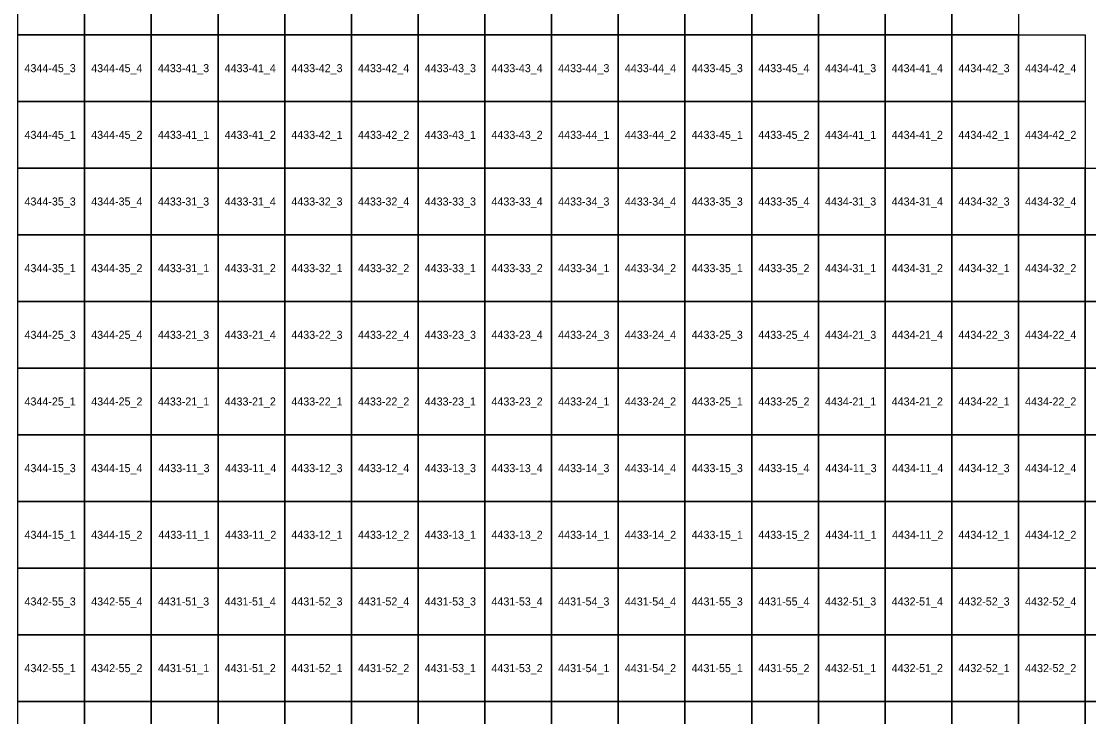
# Model space of a CAD drawing. Extents: x 312500 to 765000, y 172500 to 440000.
# Drawn here: x 595129 to 635129, y 369429 to 395507 of the extents above; entities that cross this region are included whole.
import ezdxf

# ---------------------------------------------------------------- set-up
doc = ezdxf.new("R2010")
doc.units = 0
doc.layers.add('Topo5_ramis_TKS2025', color=7, linetype='Continuous')
doc.layers.add('Topo5_ramis_TKS2025_Nr', color=7, linetype='Continuous')

msp = doc.modelspace()

# ---------------------------------------------------------------- linework, layer by layer
at = {"layer": 'Topo5_ramis_TKS2025'}
for points in [[(595000, 395000), (595000, 397500), (597500, 397500), (597500, 395000), (595000, 395000)], [(597500, 395000), (597500, 397500), (600000, 397500), (600000, 395000), (597500, 395000)], [(600000, 395000), (600000, 397500), (602500, 397500), (602500, 395000), (600000, 395000)], [(602500, 395000), (602500, 397500), (605000, 397500), (605000, 395000), (602500, 395000)], [(605000, 395000), (605000, 397500), (607500, 397500), (607500, 395000), (605000, 395000)], [(607500, 395000), (607500, 397500), (610000, 397500), (610000, 395000), (607500, 395000)], [(610000, 395000), (610000, 397500), (612500, 397500), (612500, 395000), (610000, 395000)], [(612500, 395000), (612500, 397500), (615000, 397500), (615000, 395000), (612500, 395000)], [(615000, 395000), (615000, 397500), (617500, 397500), (617500, 395000), (615000, 395000)], [(617500, 395000), (617500, 397500), (620000, 397500), (620000, 395000), (617500, 395000)], [(620000, 395000), (620000, 397500), (622500, 397500), (622500, 395000), (620000, 395000)], [(622500, 395000), (622500, 397500), (625000, 397500), (625000, 395000), (622500, 395000)], [(625000, 395000), (625000, 397500), (627500, 397500), (627500, 395000), (625000, 395000)], [(627500, 395000), (627500, 397500), (630000, 397500), (630000, 395000), (627500, 395000)], [(630000, 395000), (630000, 397500), (632500, 397500), (632500, 395000), (630000, 395000)], [(595000, 392500), (595000, 395000), (597500, 395000), (597500, 392500), (595000, 392500)], [(597500, 392500), (597500, 395000), (600000, 395000), (600000, 392500), (597500, 392500)], [(600000, 392500), (600000, 395000), (602500, 395000), (602500, 392500), (600000, 392500)], [(602500, 392500), (602500, 395000), (605000, 395000), (605000, 392500), (602500, 392500)], [(605000, 392500), (605000, 395000), (607500, 395000), (607500, 392500), (605000, 392500)], [(607500, 392500), (607500, 395000), (610000, 395000), (610000, 392500), (607500, 392500)], [(610000, 392500), (610000, 395000), (612500, 395000), (612500, 392500), (610000, 392500)], [(612500, 392500), (612500, 395000), (615000, 395000), (615000, 392500), (612500, 392500)], [(615000, 392500), (615000, 395000), (617500, 395000), (617500, 392500), (615000, 392500)], [(617500, 392500), (617500, 395000), (620000, 395000), (620000, 392500), (617500, 392500)], [(620000, 392500), (620000, 395000), (622500, 395000), (622500, 392500), (620000, 392500)], [(622500, 392500), (622500, 395000), (625000, 395000), (625000, 392500), (622500, 392500)], [(625000, 392500), (625000, 395000), (627500, 395000), (627500, 392500), (625000, 392500)], [(627500, 392500), (627500, 395000), (630000, 395000), (630000, 392500), (627500, 392500)], [(630000, 392500), (630000, 395000), (632500, 395000), (632500, 392500), (630000, 392500)], [(632500, 392500), (632500, 395000), (635000, 395000), (635000, 392500), (632500, 392500)], [(595000, 390000), (595000, 392500), (597500, 392500), (597500, 390000), (595000, 390000)], [(597500, 390000), (597500, 392500), (600000, 392500), (600000, 390000), (597500, 390000)], [(600000, 390000), (600000, 392500), (602500, 392500), (602500, 390000), (600000, 390000)], [(602500, 390000), (602500, 392500), (605000, 392500), (605000, 390000), (602500, 390000)], [(605000, 390000), (605000, 392500), (607500, 392500), (607500, 390000), (605000, 390000)], [(607500, 390000), (607500, 392500), (610000, 392500), (610000, 390000), (607500, 390000)], [(610000, 390000), (610000, 392500), (612500, 392500), (612500, 390000), (610000, 390000)], [(612500, 390000), (612500, 392500), (615000, 392500), (615000, 390000), (612500, 390000)], [(615000, 390000), (615000, 392500), (617500, 392500), (617500, 390000), (615000, 390000)], [(617500, 390000), (617500, 392500), (620000, 392500), (620000, 390000), (617500, 390000)], [(620000, 390000), (620000, 392500), (622500, 392500), (622500, 390000), (620000, 390000)], [(622500, 390000), (622500, 392500), (625000, 392500), (625000, 390000), (622500, 390000)], [(625000, 390000), (625000, 392500), (627500, 392500), (627500, 390000), (625000, 390000)], [(627500, 390000), (627500, 392500), (630000, 392500), (630000, 390000), (627500, 390000)], [(630000, 390000), (630000, 392500), (632500, 392500), (632500, 390000), (630000, 390000)], [(632500, 390000), (632500, 392500), (635000, 392500), (635000, 390000), (632500, 390000)], [(595000, 387500), (595000, 390000), (597500, 390000), (597500, 387500), (595000, 387500)], [(597500, 387500), (597500, 390000), (600000, 390000), (600000, 387500), (597500, 387500)], [(600000, 387500), (600000, 390000), (602500, 390000), (602500, 387500), (600000, 387500)], [(602500, 387500), (602500, 390000), (605000, 390000), (605000, 387500), (602500, 387500)], [(605000, 387500), (605000, 390000), (607500, 390000), (607500, 387500), (605000, 387500)], [(607500, 387500), (607500, 390000), (610000, 390000), (610000, 387500), (607500, 387500)], [(610000, 387500), (610000, 390000), (612500, 390000), (612500, 387500), (610000, 387500)], [(612500, 387500), (612500, 390000), (615000, 390000), (615000, 387500), (612500, 387500)], [(615000, 387500), (615000, 390000), (617500, 390000), (617500, 387500), (615000, 387500)], [(617500, 387500), (617500, 390000), (620000, 390000), (620000, 387500), (617500, 387500)], [(620000, 387500), (620000, 390000), (622500, 390000), (622500, 387500), (620000, 387500)], [(622500, 387500), (622500, 390000), (625000, 390000), (625000, 387500), (622500, 387500)], [(625000, 387500), (625000, 390000), (627500, 390000), (627500, 387500), (625000, 387500)], [(627500, 387500), (627500, 390000), (630000, 390000), (630000, 387500), (627500, 387500)], [(630000, 387500), (630000, 390000), (632500, 390000), (632500, 387500), (630000, 387500)], [(632500, 387500), (632500, 390000), (635000, 390000), (635000, 387500), (632500, 387500)], [(635000, 387500), (635000, 390000), (637500, 390000), (637500, 387500), (635000, 387500)], [(595000, 385000), (595000, 387500), (597500, 387500), (597500, 385000), (595000, 385000)], [(597500, 385000), (597500, 387500), (600000, 387500), (600000, 385000), (597500, 385000)], [(600000, 385000), (600000, 387500), (602500, 387500), (602500, 385000), (600000, 385000)], [(602500, 385000), (602500, 387500), (605000, 387500), (605000, 385000), (602500, 385000)], [(605000, 385000), (605000, 387500), (607500, 387500), (607500, 385000), (605000, 385000)], [(607500, 385000), (607500, 387500), (610000, 387500), (610000, 385000), (607500, 385000)], [(610000, 385000), (610000, 387500), (612500, 387500), (612500, 385000), (610000, 385000)], [(612500, 385000), (612500, 387500), (615000, 387500), (615000, 385000), (612500, 385000)], [(615000, 385000), (615000, 387500), (617500, 387500), (617500, 385000), (615000, 385000)], [(617500, 385000), (617500, 387500), (620000, 387500), (620000, 385000), (617500, 385000)], [(620000, 385000), (620000, 387500), (622500, 387500), (622500, 385000), (620000, 385000)], [(622500, 385000), (622500, 387500), (625000, 387500), (625000, 385000), (622500, 385000)], [(625000, 385000), (625000, 387500), (627500, 387500), (627500, 385000), (625000, 385000)], [(627500, 385000), (627500, 387500), (630000, 387500), (630000, 385000), (627500, 385000)], [(630000, 385000), (630000, 387500), (632500, 387500), (632500, 385000), (630000, 385000)], [(632500, 385000), (632500, 387500), (635000, 387500), (635000, 385000), (632500, 385000)], [(635000, 385000), (635000, 387500), (637500, 387500), (637500, 385000), (635000, 385000)], [(595000, 382500), (595000, 385000), (597500, 385000), (597500, 382500), (595000, 382500)], [(597500, 382500), (597500, 385000), (600000, 385000), (600000, 382500), (597500, 382500)], [(600000, 382500), (600000, 385000), (602500, 385000), (602500, 382500), (600000, 382500)], [(602500, 382500), (602500, 385000), (605000, 385000), (605000, 382500), (602500, 382500)], [(605000, 382500), (605000, 385000), (607500, 385000), (607500, 382500), (605000, 382500)], [(607500, 382500), (607500, 385000), (610000, 385000), (610000, 382500), (607500, 382500)], [(610000, 382500), (610000, 385000), (612500, 385000), (612500, 382500), (610000, 382500)], [(612500, 382500), (612500, 385000), (615000, 385000), (615000, 382500), (612500, 382500)], [(615000, 382500), (615000, 385000), (617500, 385000), (617500, 382500), (615000, 382500)], [(617500, 382500), (617500, 385000), (620000, 385000), (620000, 382500), (617500, 382500)], [(620000, 382500), (620000, 385000), (622500, 385000), (622500, 382500), (620000, 382500)], [(622500, 382500), (622500, 385000), (625000, 385000), (625000, 382500), (622500, 382500)], [(625000, 382500), (625000, 385000), (627500, 385000), (627500, 382500), (625000, 382500)], [(627500, 382500), (627500, 385000), (630000, 385000), (630000, 382500), (627500, 382500)], [(630000, 382500), (630000, 385000), (632500, 385000), (632500, 382500), (630000, 382500)], [(632500, 382500), (632500, 385000), (635000, 385000), (635000, 382500), (632500, 382500)], [(635000, 382500), (635000, 385000), (637500, 385000), (637500, 382500), (635000, 382500)], [(595000, 380000), (595000, 382500), (597500, 382500), (597500, 380000), (595000, 380000)], [(597500, 380000), (597500, 382500), (600000, 382500), (600000, 380000), (597500, 380000)], [(600000, 380000), (600000, 382500), (602500, 382500), (602500, 380000), (600000, 380000)], [(602500, 380000), (602500, 382500), (605000, 382500), (605000, 380000), (602500, 380000)], [(605000, 380000), (605000, 382500), (607500, 382500), (607500, 380000), (605000, 380000)], [(607500, 380000), (607500, 382500), (610000, 382500), (610000, 380000), (607500, 380000)], [(610000, 380000), (610000, 382500), (612500, 382500), (612500, 380000), (610000, 380000)], [(612500, 380000), (612500, 382500), (615000, 382500), (615000, 380000), (612500, 380000)], [(615000, 380000), (615000, 382500), (617500, 382500), (617500, 380000), (615000, 380000)], [(617500, 380000), (617500, 382500), (620000, 382500), (620000, 380000), (617500, 380000)], [(620000, 380000), (620000, 382500), (622500, 382500), (622500, 380000), (620000, 380000)], [(622500, 380000), (622500, 382500), (625000, 382500), (625000, 380000), (622500, 380000)], [(625000, 380000), (625000, 382500), (627500, 382500), (627500, 380000), (625000, 380000)], [(627500, 380000), (627500, 382500), (630000, 382500), (630000, 380000), (627500, 380000)], [(630000, 380000), (630000, 382500), (632500, 382500), (632500, 380000), (630000, 380000)], [(632500, 380000), (632500, 382500), (635000, 382500), (635000, 380000), (632500, 380000)], [(635000, 380000), (635000, 382500), (637500, 382500), (637500, 380000), (635000, 380000)], [(595000, 377500), (595000, 380000), (597500, 380000), (597500, 377500), (595000, 377500)], [(597500, 377500), (597500, 380000), (600000, 380000), (600000, 377500), (597500, 377500)], [(600000, 377500), (600000, 380000), (602500, 380000), (602500, 377500), (600000, 377500)], [(602500, 377500), (602500, 380000), (605000, 380000), (605000, 377500), (602500, 377500)], [(605000, 377500), (605000, 380000), (607500, 380000), (607500, 377500), (605000, 377500)], [(607500, 377500), (607500, 380000), (610000, 380000), (610000, 377500), (607500, 377500)], [(610000, 377500), (610000, 380000), (612500, 380000), (612500, 377500), (610000, 377500)], [(612500, 377500), (612500, 380000), (615000, 380000), (615000, 377500), (612500, 377500)], [(615000, 377500), (615000, 380000), (617500, 380000), (617500, 377500), (615000, 377500)], [(617500, 377500), (617500, 380000), (620000, 380000), (620000, 377500), (617500, 377500)], [(620000, 377500), (620000, 380000), (622500, 380000), (622500, 377500), (620000, 377500)], [(622500, 377500), (622500, 380000), (625000, 380000), (625000, 377500), (622500, 377500)], [(625000, 377500), (625000, 380000), (627500, 380000), (627500, 377500), (625000, 377500)], [(627500, 377500), (627500, 380000), (630000, 380000), (630000, 377500), (627500, 377500)], [(630000, 377500), (630000, 380000), (632500, 380000), (632500, 377500), (630000, 377500)], [(632500, 377500), (632500, 380000), (635000, 380000), (635000, 377500), (632500, 377500)], [(635000, 377500), (635000, 380000), (637500, 380000), (637500, 377500), (635000, 377500)], [(595000, 375000), (595000, 377500), (597500, 377500), (597500, 375000), (595000, 375000)], [(597500, 375000), (597500, 377500), (600000, 377500), (600000, 375000), (597500, 375000)], [(600000, 375000), (600000, 377500), (602500, 377500), (602500, 375000), (600000, 375000)], [(602500, 375000), (602500, 377500), (605000, 377500), (605000, 375000), (602500, 375000)], [(605000, 375000), (605000, 377500), (607500, 377500), (607500, 375000), (605000, 375000)], [(607500, 375000), (607500, 377500), (610000, 377500), (610000, 375000), (607500, 375000)], [(610000, 375000), (610000, 377500), (612500, 377500), (612500, 375000), (610000, 375000)], [(612500, 375000), (612500, 377500), (615000, 377500), (615000, 375000), (612500, 375000)], [(615000, 375000), (615000, 377500), (617500, 377500), (617500, 375000), (615000, 375000)], [(617500, 375000), (617500, 377500), (620000, 377500), (620000, 375000), (617500, 375000)], [(620000, 375000), (620000, 377500), (622500, 377500), (622500, 375000), (620000, 375000)], [(622500, 375000), (622500, 377500), (625000, 377500), (625000, 375000), (622500, 375000)], [(625000, 375000), (625000, 377500), (627500, 377500), (627500, 375000), (625000, 375000)], [(627500, 375000), (627500, 377500), (630000, 377500), (630000, 375000), (627500, 375000)], [(630000, 375000), (630000, 377500), (632500, 377500), (632500, 375000), (630000, 375000)], [(632500, 375000), (632500, 377500), (635000, 377500), (635000, 375000), (632500, 375000)], [(635000, 375000), (635000, 377500), (637500, 377500), (637500, 375000), (635000, 375000)], [(595000, 372500), (595000, 375000), (597500, 375000), (597500, 372500), (595000, 372500)], [(597500, 372500), (597500, 375000), (600000, 375000), (600000, 372500), (597500, 372500)], [(600000, 372500), (600000, 375000), (602500, 375000), (602500, 372500), (600000, 372500)], [(602500, 372500), (602500, 375000), (605000, 375000), (605000, 372500), (602500, 372500)], [(605000, 372500), (605000, 375000), (607500, 375000), (607500, 372500), (605000, 372500)], [(607500, 372500), (607500, 375000), (610000, 375000), (610000, 372500), (607500, 372500)], [(610000, 372500), (610000, 375000), (612500, 375000), (612500, 372500), (610000, 372500)], [(612500, 372500), (612500, 375000), (615000, 375000), (615000, 372500), (612500, 372500)], [(615000, 372500), (615000, 375000), (617500, 375000), (617500, 372500), (615000, 372500)], [(617500, 372500), (617500, 375000), (620000, 375000), (620000, 372500), (617500, 372500)], [(620000, 372500), (620000, 375000), (622500, 375000), (622500, 372500), (620000, 372500)], [(622500, 372500), (622500, 375000), (625000, 375000), (625000, 372500), (622500, 372500)], [(625000, 372500), (625000, 375000), (627500, 375000), (627500, 372500), (625000, 372500)], [(627500, 372500), (627500, 375000), (630000, 375000), (630000, 372500), (627500, 372500)], [(630000, 372500), (630000, 375000), (632500, 375000), (632500, 372500), (630000, 372500)], [(632500, 372500), (632500, 375000), (635000, 375000), (635000, 372500), (632500, 372500)], [(635000, 372500), (635000, 375000), (637500, 375000), (637500, 372500), (635000, 372500)], [(595000, 370000), (595000, 372500), (597500, 372500), (597500, 370000), (595000, 370000)], [(597500, 370000), (597500, 372500), (600000, 372500), (600000, 370000), (597500, 370000)], [(600000, 370000), (600000, 372500), (602500, 372500), (602500, 370000), (600000, 370000)], [(602500, 370000), (602500, 372500), (605000, 372500), (605000, 370000), (602500, 370000)], [(605000, 370000), (605000, 372500), (607500, 372500), (607500, 370000), (605000, 370000)], [(607500, 370000), (607500, 372500), (610000, 372500), (610000, 370000), (607500, 370000)], [(610000, 370000), (610000, 372500), (612500, 372500), (612500, 370000), (610000, 370000)], [(612500, 370000), (612500, 372500), (615000, 372500), (615000, 370000), (612500, 370000)], [(615000, 370000), (615000, 372500), (617500, 372500), (617500, 370000), (615000, 370000)], [(617500, 370000), (617500, 372500), (620000, 372500), (620000, 370000), (617500, 370000)], [(620000, 370000), (620000, 372500), (622500, 372500), (622500, 370000), (620000, 370000)], [(622500, 370000), (622500, 372500), (625000, 372500), (625000, 370000), (622500, 370000)], [(625000, 370000), (625000, 372500), (627500, 372500), (627500, 370000), (625000, 370000)], [(627500, 370000), (627500, 372500), (630000, 372500), (630000, 370000), (627500, 370000)], [(630000, 370000), (630000, 372500), (632500, 372500), (632500, 370000), (630000, 370000)], [(632500, 370000), (632500, 372500), (635000, 372500), (635000, 370000), (632500, 370000)], [(635000, 370000), (635000, 372500), (637500, 372500), (637500, 370000), (635000, 370000)], [(595000, 367500), (595000, 370000), (597500, 370000), (597500, 367500), (595000, 367500)], [(597500, 367500), (597500, 370000), (600000, 370000), (600000, 367500), (597500, 367500)], [(600000, 367500), (600000, 370000), (602500, 370000), (602500, 367500), (600000, 367500)], [(602500, 367500), (602500, 370000), (605000, 370000), (605000, 367500), (602500, 367500)], [(605000, 367500), (605000, 370000), (607500, 370000), (607500, 367500), (605000, 367500)], [(607500, 367500), (607500, 370000), (610000, 370000), (610000, 367500), (607500, 367500)], [(610000, 367500), (610000, 370000), (612500, 370000), (612500, 367500), (610000, 367500)], [(612500, 367500), (612500, 370000), (615000, 370000), (615000, 367500), (612500, 367500)], [(615000, 367500), (615000, 370000), (617500, 370000), (617500, 367500), (615000, 367500)], [(617500, 367500), (617500, 370000), (620000, 370000), (620000, 367500), (617500, 367500)], [(620000, 367500), (620000, 370000), (622500, 370000), (622500, 367500), (620000, 367500)], [(622500, 367500), (622500, 370000), (625000, 370000), (625000, 367500), (622500, 367500)], [(625000, 367500), (625000, 370000), (627500, 370000), (627500, 367500), (625000, 367500)], [(627500, 367500), (627500, 370000), (630000, 370000), (630000, 367500), (627500, 367500)], [(630000, 367500), (630000, 370000), (632500, 370000), (632500, 367500), (630000, 367500)], [(632500, 367500), (632500, 370000), (635000, 370000), (635000, 367500), (632500, 367500)], [(635000, 367500), (635000, 370000), (637500, 370000), (637500, 367500), (635000, 367500)]]:
    msp.add_lwpolyline(points, dxfattribs=at)

# ---------------------------------------------------------------- texts
at = {"layer": 'Topo5_ramis_TKS2025_Nr'}
for s, p in [('4344-45_3', (595248, 393600)), ('4344-45_4', (597748, 393600)), ('4433-41_3', (600248, 393600)), ('4433-41_4', (602748, 393600)), ('4433-42_3', (605248, 393600)), ('4433-42_4', (607748, 393600)), ('4433-43_3', (610248, 393600)), ('4433-43_4', (612748, 393600)), ('4433-44_3', (615248, 393600)), ('4433-44_4', (617748, 393600)), ('4433-45_3', (620248, 393600)), ('4433-45_4', (622748, 393600)), ('4434-41_3', (625248, 393600)), ('4434-41_4', (627748, 393600)), ('4434-42_3', (630248, 393600)), ('4434-42_4', (632748, 393600)), ('4344-45_1', (595248, 391100)), ('4344-45_2', (597748, 391100)), ('4433-41_1', (600248, 391100)), ('4433-41_2', (602748, 391100)), ('4433-42_1', (605248, 391100)), ('4433-42_2', (607748, 391100)), ('4433-43_1', (610248, 391100)), ('4433-43_2', (612748, 391100)), ('4433-44_1', (615248, 391100)), ('4433-44_2', (617748, 391100)), ('4433-45_1', (620248, 391100)), ('4433-45_2', (622748, 391100)), ('4434-41_1', (625248, 391100)), ('4434-41_2', (627748, 391100)), ('4434-42_1', (630248, 391100)), ('4434-42_2', (632748, 391100)), ('4344-35_3', (595248, 388600)), ('4344-35_4', (597748, 388600)), ('4433-31_3', (600248, 388600)), ('4433-31_4', (602748, 388600)), ('4433-32_3', (605248, 388600)), ('4433-32_4', (607748, 388600)), ('4433-33_3', (610248, 388600)), ('4433-33_4', (612748, 388600)), ('4433-34_3', (615248, 388600)), ('4433-34_4', (617748, 388600)), ('4433-35_3', (620248, 388600)), ('4433-35_4', (622748, 388600)), ('4434-31_3', (625248, 388600)), ('4434-31_4', (627748, 388600)), ('4434-32_3', (630248, 388600)), ('4434-32_4', (632748, 388600)), ('4344-35_1', (595248, 386100)), ('4344-35_2', (597748, 386100)), ('4433-31_1', (600248, 386100)), ('4433-31_2', (602748, 386100)), ('4433-32_1', (605248, 386100)), ('4433-32_2', (607748, 386100)), ('4433-33_1', (610248, 386100)), ('4433-33_2', (612748, 386100)), ('4433-34_1', (615248, 386100)), ('4433-34_2', (617748, 386100)), ('4433-35_1', (620248, 386100)), ('4433-35_2', (622748, 386100)), ('4434-31_1', (625248, 386100)), ('4434-31_2', (627748, 386100)), ('4434-32_1', (630248, 386100)), ('4434-32_2', (632748, 386100)), ('4344-25_3', (595248, 383600)), ('4344-25_4', (597748, 383600)), ('4433-21_3', (600248, 383600)), ('4433-21_4', (602748, 383600)), ('4433-22_3', (605248, 383600)), ('4433-22_4', (607748, 383600)), ('4433-23_3', (610248, 383600)), ('4433-23_4', (612748, 383600)), ('4433-24_3', (615248, 383600)), ('4433-24_4', (617748, 383600)), ('4433-25_3', (620248, 383600)), ('4433-25_4', (622748, 383600)), ('4434-21_3', (625248, 383600)), ('4434-21_4', (627748, 383600)), ('4434-22_3', (630248, 383600)), ('4434-22_4', (632748, 383600)), ('4344-25_1', (595248, 381100)), ('4344-25_2', (597748, 381100)), ('4433-21_1', (600248, 381100)), ('4433-21_2', (602748, 381100)), ('4433-22_1', (605248, 381100)), ('4433-22_2', (607748, 381100)), ('4433-23_1', (610248, 381100)), ('4433-23_2', (612748, 381100)), ('4433-24_1', (615248, 381100)), ('4433-24_2', (617748, 381100)), ('4433-25_1', (620248, 381100)), ('4433-25_2', (622748, 381100)), ('4434-21_1', (625248, 381100)), ('4434-21_2', (627748, 381100)), ('4434-22_1', (630248, 381100)), ('4434-22_2', (632748, 381100)), ('4344-15_3', (595248, 378600)), ('4344-15_4', (597748, 378600)), ('4433-11_3', (600264, 378600)), ('4433-11_4', (602764, 378600)), ('4433-12_3', (605248, 378600)), ('4433-12_4', (607748, 378600)), ('4433-13_3', (610248, 378600)), ('4433-13_4', (612748, 378600)), ('4433-14_3', (615248, 378600)), ('4433-14_4', (617748, 378600)), ('4433-15_3', (620248, 378600)), ('4433-15_4', (622748, 378600)), ('4434-11_3', (625264, 378600)), ('4434-11_4', (627764, 378600)), ('4434-12_3', (630248, 378600)), ('4434-12_4', (632748, 378600)), ('4344-15_1', (595248, 376100)), ('4344-15_2', (597748, 376100)), ('4433-11_1', (600264, 376100)), ('4433-11_2', (602764, 376100)), ('4433-12_1', (605248, 376100)), ('4433-12_2', (607748, 376100)), ('4433-13_1', (610248, 376100)), ('4433-13_2', (612748, 376100)), ('4433-14_1', (615248, 376100)), ('4433-14_2', (617748, 376100)), ('4433-15_1', (620248, 376100)), ('4433-15_2', (622748, 376100)), ('4434-11_1', (625264, 376100)), ('4434-11_2', (627764, 376100)), ('4434-12_1', (630248, 376100)), ('4434-12_2', (632748, 376100)), ('4342-55_3', (595248, 373600)), ('4342-55_4', (597748, 373600)), ('4431-51_3', (600248, 373600)), ('4431-51_4', (602748, 373600)), ('4431-52_3', (605248, 373600)), ('4431-52_4', (607748, 373600)), ('4431-53_3', (610248, 373600)), ('4431-53_4', (612748, 373600)), ('4431-54_3', (615248, 373600)), ('4431-54_4', (617748, 373600)), ('4431-55_3', (620248, 373600)), ('4431-55_4', (622748, 373600)), ('4432-51_3', (625248, 373600)), ('4432-51_4', (627748, 373600)), ('4432-52_3', (630248, 373600)), ('4432-52_4', (632748, 373600)), ('4342-55_1', (595248, 371100)), ('4342-55_2', (597748, 371100)), ('4431-51_1', (600248, 371100)), ('4431-51_2', (602748, 371100)), ('4431-52_1', (605248, 371100)), ('4431-52_2', (607748, 371100)), ('4431-53_1', (610248, 371100)), ('4431-53_2', (612748, 371100)), ('4431-54_1', (615248, 371100)), ('4431-54_2', (617748, 371100)), ('4431-55_1', (620248, 371100)), ('4431-55_2', (622748, 371100)), ('4432-51_1', (625248, 371100)), ('4432-51_2', (627748, 371100)), ('4432-52_1', (630248, 371100)), ('4432-52_2', (632748, 371100))]:
    msp.add_text(s, height=300, dxfattribs=at).set_placement(p)

doc.saveas('drawing.dxf')
